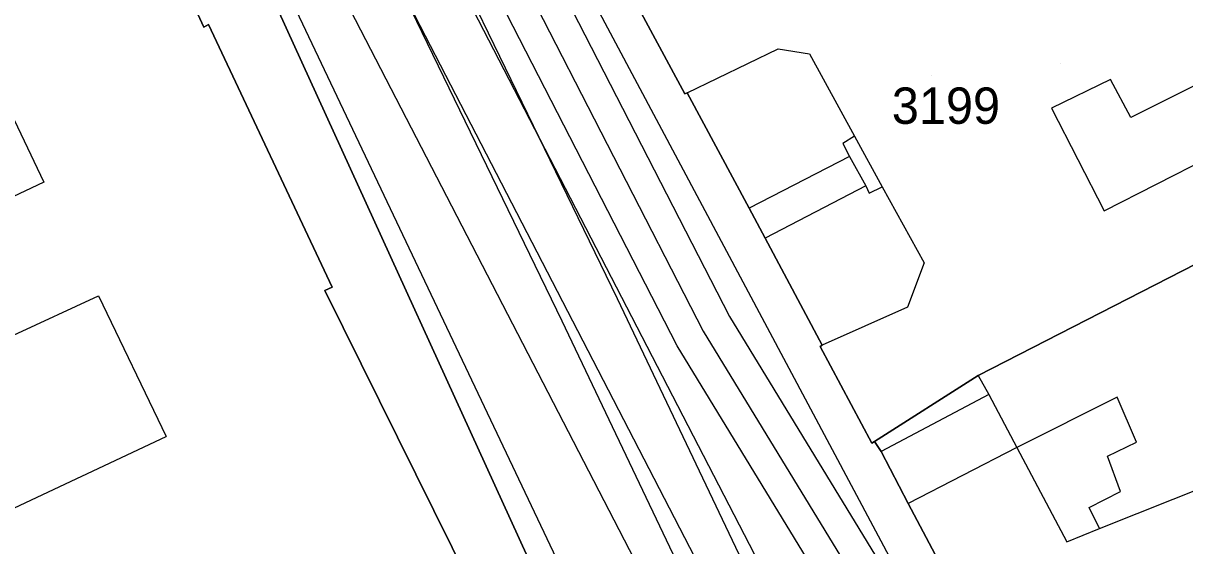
# Model space of a CAD drawing. Extents: x -264070 to -262271, y -1238894 to -1238141.
# Drawn here: x -263128.8 to -263064.9, y -1238732.8 to -1238704 of the extents above; entities that cross this region are included whole.
import ezdxf

# ---------------------------------------------------------------- set-up
doc = ezdxf.new("R2010")
doc.units = 0
for name, color, linetype in [('body_kn', 7, 'Continuous'), ('kladpar_druhypozemkov', 7, 'Continuous'), ('kladpar_hranice', 7, 'Continuous'), ('kladpar_parcelnecisla', 7, 'Continuous'), ('kladpar_plochy', 7, 'Continuous'), ('linie', 7, 'Continuous'), ('tarchy_linie', 7, 'Continuous'), ('zappar_hrandruhpozemk', 7, 'Continuous'), ('znacky', 7, 'Continuous')]:
    doc.layers.add(name, color=color, linetype=linetype)

msp = doc.modelspace()

# ---------------------------------------------------------------- linework, layer by layer
at = {"layer": 'body_kn'}
for p, q in [((-263118.84, -1238704.23), (-263118.84, -1238704.23)), ((-263118.58, -1238704.07), (-263118.58, -1238704.07)), ((-263087.27, -1238705.42), (-263087.27, -1238705.42)), ((-263085.53, -1238705.69), (-263085.53, -1238705.69)), ((-263069, -1238707.1), (-263069, -1238707.1)), ((-263092.26, -1238707.84), (-263092.26, -1238707.84)), ((-263092.26, -1238707.84), (-263092.26, -1238707.84)), ((-263092.39, -1238707.89), (-263092.39, -1238707.89)), ((-263072.23, -1238708.67), (-263072.23, -1238708.67)), ((-263067.88, -1238709.19), (-263067.88, -1238709.19)), ((-263083.06, -1238710.21), (-263083.06, -1238710.21)), ((-263083.7, -1238710.63), (-263083.7, -1238710.63)), ((-263083.34, -1238711.34), (-263083.34, -1238711.34)), ((-263083.34, -1238711.34), (-263083.34, -1238711.34)), ((-263127.62, -1238712.74), (-263127.62, -1238712.74)), ((-263082.45, -1238712.95), (-263082.45, -1238712.95)), ((-263082.45, -1238712.95), (-263082.45, -1238712.95)), ((-263082.26, -1238713.36), (-263082.26, -1238713.36)), ((-263081.55, -1238713.01), (-263081.55, -1238713.01)), ((-263088.85, -1238714.18), (-263088.85, -1238714.18)), ((-263069.34, -1238714.33), (-263069.34, -1238714.33)), ((-263087.98, -1238715.82), (-263087.98, -1238715.82)), ((-263079.24, -1238717.18), (-263079.24, -1238717.18)), ((-263112.18, -1238718.71), (-263112.18, -1238718.71)), ((-263111.78, -1238718.52), (-263111.78, -1238718.52)), ((-263111.78, -1238718.52), (-263111.78, -1238718.52)), ((-263124.62, -1238719), (-263124.62, -1238719)), ((-263124.62, -1238719), (-263124.62, -1238719)), ((-263096.1, -1238719.17), (-263096.1, -1238719.17)), ((-263080.16, -1238719.62), (-263080.16, -1238719.62)), ((-263099.15, -1238720.37), (-263099.15, -1238720.37)), ((-263089.94, -1238720.14), (-263089.94, -1238720.14)), ((-263091.38, -1238720.95), (-263091.38, -1238720.95)), ((-263092.82, -1238721.76), (-263092.82, -1238721.76)), ((-263084.95, -1238721.79), (-263084.95, -1238721.79)), ((-263084.85, -1238721.71), (-263084.85, -1238721.71)), ((-263076.26, -1238723.39), (-263076.26, -1238723.39)), ((-263076.26, -1238723.39), (-263076.26, -1238723.39)), ((-263075.68, -1238724.43), (-263075.68, -1238724.43)), ((-263075.68, -1238724.43), (-263075.68, -1238724.43)), ((-263068.63, -1238724.58), (-263068.63, -1238724.58)), ((-263120.91, -1238726.73), (-263120.91, -1238726.73)), ((-263081.96, -1238727.02), (-263081.96, -1238727.02)), ((-263082.12, -1238727.11), (-263082.12, -1238727.11)), ((-263081.6, -1238727.57), (-263081.6, -1238727.57)), ((-263074.15, -1238727.34), (-263074.15, -1238727.34)), ((-263074.15, -1238727.34), (-263074.15, -1238727.34)), ((-263067.57, -1238727.05), (-263067.57, -1238727.05)), ((-263069.15, -1238727.82), (-263069.15, -1238727.82)), ((-263068.44, -1238729.77), (-263068.44, -1238729.77)), ((-263080.11, -1238730.42), (-263080.11, -1238730.42)), ((-263070.16, -1238730.64), (-263070.16, -1238730.64)), ((-263069.6, -1238731.8), (-263069.6, -1238731.8)), ((-263071.39, -1238732.53), (-263071.39, -1238732.53))]:
    msp.add_line(p, q, dxfattribs=at)
at = {"layer": 'kladpar_druhypozemkov'}
msp.add_line((-263078.84, -1238706.86), (-263078.84, -1238706.86), dxfattribs=at)
at = {"layer": 'kladpar_hranice'}
for points in [[(-263114.78, -1238664.6), (-263107.67, -1238678.23), (-263095.18, -1238702.44), (-263095.29, -1238702.5), (-263092.39, -1238707.89), (-263092.26, -1238707.84), (-263088.85, -1238714.18), (-263087.98, -1238715.82), (-263084.85, -1238721.71), (-263084.95, -1238721.79), (-263082.12, -1238727.11), (-263081.96, -1238727.02), (-263081.6, -1238727.57), (-263080.11, -1238730.42), (-263073.98, -1238742.03)], [(-263129.14, -1238681.78), (-263127.56, -1238682.27), (-263125.91, -1238682.87), (-263124.83, -1238683.52), (-263124.11, -1238684.02), (-263123.56, -1238684.56), (-263122.71, -1238685.8), (-263091.36, -1238754.57), (-263090.45, -1238756.44), (-263093.7, -1238757.59), (-263093.54, -1238756.9), (-263095.66, -1238751.51), (-263095.28, -1238751.31), (-263102.69, -1238736.62), (-263103.19, -1238736.88), (-263112.18, -1238718.71), (-263111.78, -1238718.52), (-263118.58, -1238704.07), (-263118.84, -1238704.23), (-263123.13, -1238694.87), (-263123.66, -1238694.17), (-263125.06, -1238690.95), (-263135.82, -1238694.26)], [(-263091.36, -1238754.57), (-263122.71, -1238685.8), (-263123.56, -1238684.56), (-263124.11, -1238684.02), (-263124.83, -1238683.52), (-263125.91, -1238682.87), (-263127.56, -1238682.27), (-263129.14, -1238681.78)], [(-263060.57, -1238715.33), (-263076.26, -1238723.39), (-263081.96, -1238727.02), (-263082.12, -1238727.11), (-263084.95, -1238721.79), (-263084.85, -1238721.71), (-263087.98, -1238715.82), (-263088.85, -1238714.18), (-263092.26, -1238707.84), (-263092.39, -1238707.89), (-263095.29, -1238702.5), (-263095.18, -1238702.44), (-263092.27, -1238700.7), (-263084.02, -1238695.9), (-263083.38, -1238695.58), (-263076.91, -1238692.1), (-263073.56, -1238690.37), (-263071.86, -1238689.44), (-263058.06, -1238682.52)], [(-263147.67, -1238703), (-263125.04, -1238694.73), (-263123.66, -1238694.17), (-263123.13, -1238694.87), (-263118.84, -1238704.23), (-263118.58, -1238704.07), (-263111.78, -1238718.52)], [(-263059.42, -1238743.97), (-263065.03, -1238746.31), (-263065.24, -1238745.93), (-263070.69, -1238748.25), (-263073.98, -1238742.03), (-263080.11, -1238730.42), (-263081.6, -1238727.57), (-263081.96, -1238727.02), (-263076.26, -1238723.39), (-263060.57, -1238715.33)], [(-263111.78, -1238718.52), (-263112.18, -1238718.71), (-263103.19, -1238736.88), (-263102.69, -1238736.62), (-263095.28, -1238751.31), (-263095.66, -1238751.51), (-263093.54, -1238756.9), (-263093.7, -1238757.59), (-263103.22, -1238761.22), (-263103.15, -1238761.72), (-263119.6, -1238768.18), (-263119.79, -1238767.71), (-263129.74, -1238771.43)]]:
    msp.add_lwpolyline(points, dxfattribs=at)
at = {"layer": 'kladpar_plochy'}
for points in [[(-263114.78, -1238664.6), (-263107.67, -1238678.23), (-263095.18, -1238702.44), (-263095.29, -1238702.5), (-263092.39, -1238707.89), (-263092.26, -1238707.84), (-263088.85, -1238714.18), (-263087.98, -1238715.82), (-263084.85, -1238721.71), (-263084.95, -1238721.79), (-263082.12, -1238727.11), (-263081.96, -1238727.02), (-263081.6, -1238727.57), (-263080.11, -1238730.42), (-263073.98, -1238742.03)], [(-263129.14, -1238681.78), (-263127.56, -1238682.27), (-263125.91, -1238682.87), (-263124.83, -1238683.52), (-263124.11, -1238684.02), (-263123.56, -1238684.56), (-263122.71, -1238685.8), (-263091.36, -1238754.57), (-263090.45, -1238756.44), (-263093.7, -1238757.59), (-263093.54, -1238756.9), (-263095.66, -1238751.51), (-263095.28, -1238751.31), (-263102.69, -1238736.62), (-263103.19, -1238736.88), (-263112.18, -1238718.71), (-263111.78, -1238718.52), (-263118.58, -1238704.07), (-263118.84, -1238704.23), (-263123.13, -1238694.87), (-263123.66, -1238694.17), (-263125.06, -1238690.95), (-263135.82, -1238694.26)], [(-263091.36, -1238754.57), (-263122.71, -1238685.8), (-263123.56, -1238684.56), (-263124.11, -1238684.02), (-263124.83, -1238683.52), (-263125.91, -1238682.87), (-263127.56, -1238682.27), (-263129.14, -1238681.78)], [(-263060.57, -1238715.33), (-263076.26, -1238723.39), (-263081.96, -1238727.02), (-263082.12, -1238727.11), (-263084.95, -1238721.79), (-263084.85, -1238721.71), (-263087.98, -1238715.82), (-263088.85, -1238714.18), (-263092.26, -1238707.84), (-263092.39, -1238707.89), (-263095.29, -1238702.5), (-263095.18, -1238702.44), (-263092.27, -1238700.7), (-263084.02, -1238695.9), (-263083.38, -1238695.58), (-263076.91, -1238692.1), (-263073.56, -1238690.37), (-263071.86, -1238689.44), (-263058.06, -1238682.52)], [(-263147.67, -1238703), (-263125.04, -1238694.73), (-263123.66, -1238694.17), (-263123.13, -1238694.87), (-263118.84, -1238704.23), (-263118.58, -1238704.07), (-263111.78, -1238718.52), (-263112.18, -1238718.71), (-263103.19, -1238736.88), (-263102.69, -1238736.62), (-263095.28, -1238751.31), (-263095.66, -1238751.51), (-263093.54, -1238756.9), (-263093.7, -1238757.59), (-263103.22, -1238761.22), (-263103.15, -1238761.72), (-263119.6, -1238768.18), (-263119.79, -1238767.71), (-263129.74, -1238771.43)], [(-263059.42, -1238743.97), (-263065.03, -1238746.31), (-263065.24, -1238745.93), (-263070.69, -1238748.25), (-263073.98, -1238742.03), (-263080.11, -1238730.42), (-263081.6, -1238727.57), (-263081.96, -1238727.02), (-263076.26, -1238723.39), (-263060.57, -1238715.33)]]:
    msp.add_lwpolyline(points, dxfattribs=at)
at = {"layer": 'linie'}
for points in [[(-263063.04, -1238778.77), (-263068.07, -1238773.45), (-263069.96, -1238771.12), (-263071.69, -1238768.72), (-263073.33, -1238766.21), (-263074.8, -1238763.65), (-263076.42, -1238760.55), (-263096.1, -1238719.17), (-263105.96, -1238698.83), (-263116.74, -1238677.78), (-263123.83, -1238664.51), (-263311.16, -1238317.88)], [(-263314.1, -1238319.26), (-263126.88, -1238665.7), (-263119.71, -1238679.15), (-263108.92, -1238700.2), (-263099.15, -1238720.37), (-263079.37, -1238761.95), (-263077.78, -1238765.06), (-263075.53, -1238768.91), (-263073.84, -1238771.47), (-263071.58, -1238774.58), (-263069.26, -1238777.45), (-263064.54, -1238782.61), (-263056.93, -1238790.48)]]:
    msp.add_lwpolyline(points, dxfattribs=at)
at = {"layer": 'tarchy_linie'}
for points in [[(-263306.98, -1238315.92), (-263306.6, -1238316.59), (-263302.8, -1238323.82), (-263301.41, -1238326.15), (-263270.64, -1238376.15), (-263263.37, -1238386.67), (-263261.46, -1238390.56), (-263222, -1238460.08), (-263200.09, -1238504.27), (-263177.47, -1238551.04), (-263170.64, -1238565.5), (-263170.37, -1238566.1), (-263170.32, -1238569.13), (-263168.26, -1238573.07), (-263162.41, -1238584.29), (-263153.56, -1238601.85), (-263144.13, -1238620.13), (-263134.07, -1238638.61), (-263131.09, -1238643.78), (-263111.1, -1238682.49), (-263091.38, -1238720.95), (-263073.9, -1238749.61)], [(-263306.67, -1238319.58), (-263291.43, -1238347.22), (-263285.01, -1238357.3), (-263264.62, -1238388.84), (-263262.08, -1238392.76), (-263243.7, -1238427.74), (-263231.89, -1238445.21), (-263223.86, -1238461.1), (-263200.63, -1238506.42), (-263194.06, -1238522.96), (-263163.73, -1238584.79), (-263134.84, -1238647.42), (-263107.24, -1238703.6), (-263081.79, -1238752.86)], [(-263130.42, -1238641.63), (-263128.07, -1238640.35), (-263127.9, -1238640.35), (-263127.07, -1238640.31), (-263126.6, -1238641.32), (-263125.78, -1238643.09), (-263125.06, -1238644.64), (-263128.05, -1238646.06), (-263109.63, -1238681.74), (-263089.94, -1238720.14), (-263072.37, -1238748.97), (-263072.75, -1238749.13), (-263073.9, -1238749.61), (-263075.44, -1238750.24), (-263092.82, -1238721.76), (-263112.57, -1238683.24), (-263131.03, -1238647.49)], [(-263131.52, -1238647.72), (-263105.81, -1238700.05), (-263105.72, -1238700), (-263079.01, -1238751.72), (-263081.79, -1238752.86), (-263084.57, -1238754.01), (-263111.05, -1238702.76), (-263110.87, -1238702.67), (-263138.5, -1238646.43)]]:
    msp.add_lwpolyline(points, dxfattribs=at)
at = {"layer": 'zappar_hrandruhpozemk'}
for p, q in [((-263090.08, -1238753.19), (-263121.84, -1238686.25)), ((-263072.75, -1238749.13), (-263101.61, -1238694.9)), ((-263053.39, -1238701.92), (-263067.88, -1238709.19)), ((-263083.34, -1238711.34), (-263088.85, -1238714.18)), ((-263082.45, -1238712.95), (-263087.98, -1238715.82)), ((-263124.62, -1238719), (-263120.91, -1238726.73)), ((-263075.68, -1238724.43), (-263081.6, -1238727.57)), ((-263068.63, -1238724.58), (-263074.15, -1238727.34)), ((-263067.57, -1238727.05), (-263068.63, -1238724.58)), ((-263133.63, -1238732.72), (-263120.91, -1238726.73)), ((-263074.15, -1238727.34), (-263080.11, -1238730.42)), ((-263069.6, -1238731.8), (-263060.52, -1238728.19))]:
    msp.add_line(p, q, dxfattribs=at)
for points in [[(-263131.26, -1238705.15), (-263127.62, -1238712.74), (-263132.09, -1238714.86), (-263133.09, -1238717.85), (-263131.93, -1238720.16), (-263129.29, -1238721.16), (-263124.62, -1238719)], [(-263092.26, -1238707.84), (-263087.27, -1238705.42), (-263085.53, -1238705.69), (-263083.06, -1238710.21)], [(-263067.88, -1238709.19), (-263069, -1238707.1), (-263072.23, -1238708.67), (-263069.34, -1238714.33), (-263063.58, -1238711.4), (-263062.51, -1238710.87)], [(-263083.06, -1238710.21), (-263083.7, -1238710.63), (-263083.34, -1238711.34), (-263082.45, -1238712.95), (-263082.26, -1238713.36), (-263081.55, -1238713.01)], [(-263083.06, -1238710.21), (-263081.55, -1238713.01), (-263079.24, -1238717.18)], [(-263079.24, -1238717.18), (-263080.16, -1238719.62), (-263084.85, -1238721.71)], [(-263076.26, -1238723.39), (-263075.68, -1238724.43), (-263074.15, -1238727.34), (-263071.39, -1238732.53), (-263069.6, -1238731.8)], [(-263069.6, -1238731.8), (-263070.16, -1238730.64), (-263068.44, -1238729.77), (-263069.15, -1238727.82), (-263067.57, -1238727.05)]]:
    msp.add_lwpolyline(points, dxfattribs=at)
at = {"layer": 'znacky'}
msp.add_line((-263071.73, -1238706.23), (-263071.73, -1238706.23), dxfattribs=at)

# ---------------------------------------------------------------- texts
at = {"layer": 'kladpar_parcelnecisla'}
msp.add_text('3199', height=2, dxfattribs=at).set_placement((-263081.013, -1238709.54))

doc.saveas('drawing.dxf')
